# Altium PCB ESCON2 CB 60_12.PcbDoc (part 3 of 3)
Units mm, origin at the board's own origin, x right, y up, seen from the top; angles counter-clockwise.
Board outline 65.5 x 41 mm, 8 copper layers (Top Side, Mid Layer 1, Mid Layer 2, Mid Layer 3, Mid Layer 4, Mid Layer 5, Mid Layer 6, Bottom Side), stack 1.555 mm thick; 142 components, 77 nets, 455 pads, 2194 vias.
Unrouted connection lines stored in the file: 71.
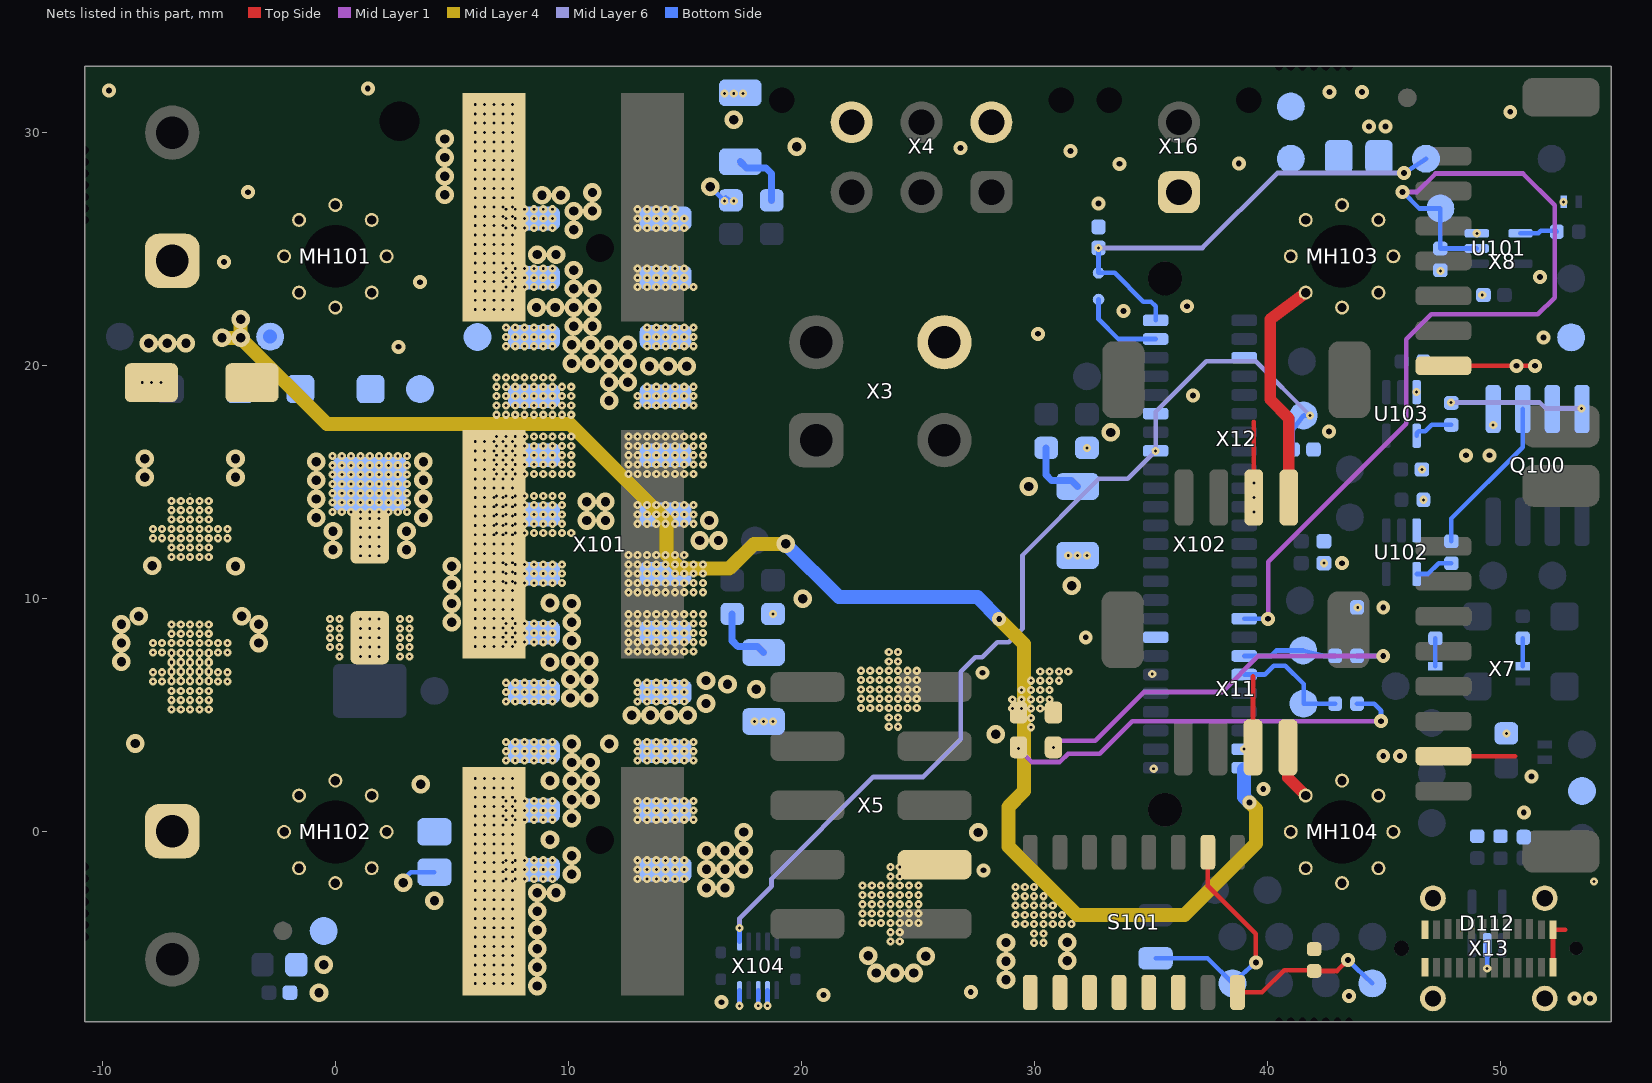
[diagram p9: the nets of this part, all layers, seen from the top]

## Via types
v1: diameter 0.35, hole 0.125, Mid Layer 6 to Bottom Side, tented both sides, 1058 vias
v2: diameter 0.35, hole 0.125, Top Side to Mid Layer 1, tented both sides, 820 vias
v3: diameter 0.8, hole 0.4, Top Side to Bottom Side, 205 vias
v4: diameter 0.6, hole 0.25, Top Side to Bottom Side, 111 vias

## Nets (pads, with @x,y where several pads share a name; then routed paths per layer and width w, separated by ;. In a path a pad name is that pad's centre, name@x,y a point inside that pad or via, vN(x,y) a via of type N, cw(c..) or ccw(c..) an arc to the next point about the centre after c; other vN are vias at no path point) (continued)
GND: C101.2 C102.2 C103.2 C104.2 C106.1 C108.1 C112.1 C113.1 C114.1 C115.1 C116.1 C119.1 C122.1 C123.1 C124.1 C125.1 C126.2 D101.2 D104.2 D106.1 D112.2 D113.1 D114.1 DS101.1 DS102.1 Q100.1 Q100.3 R102.1 R103.1 R105.1 R107.2 R108.2 R117.1 R118.1 R119.1 R120.1 R121.1 S101.1 S101.2 S101.3 S101.4 S101.5 S101.6 TP101.1 TP116.1 TP125.1 TP149.1 U101.3 U102.3 U103.3 X1.1 X2.1 X4.4 X5.3 X7.7 X8.7 X11.3 X12.3 X13.A1 X13.A12 X13.B1 X13.B12 X16.1 X101.1 X101.7 X101.13 X101.23 X101.24 X102.3 X102.16 X102.40 X102.45 X104.3 X104.5 X104.9 | length 20.4
  Top Side w0.2: X11.3@39.379,3.625 39.379,6.685 ; v2(39.415,14.972) 39.415,17.599 ; X7.7@47.55,3.25 50.624,3.25 ; X8.7@47.55,20 v4(50.687,20) v4(51.477,20) ; X13.B1@52.25,-5.805 X13.A12@52.25,-4.195 52.779,-4.195
  Bottom Side w0.2: v3@2.872,-2.088 3.231,-1.73 C108.1@4.25,-1.73 ; v3(16.083,27.687) 16.693,27.076 v1(16.697,27.076) ; C113.1@16.747,27.221 ccw(c17.097,27.572) v1(17.097,27.076) ; v1@17.345,-7.384 X104.9@17.345,-6.795 ; v1@18.145,-7.38 X104.5@18.145,-6.795 ; v1@18.545,-7.38 X104.3@18.545,-6.795 ; v1(49.429,-5.86) D112.2@49.429,-4.867 ; v4@51.292,2.382 v4(51.325,2.382)
  other v1: 17.345,-7.464 18.145,-7.46 18.545,-7.46 29.985,-4.76 30.385,-4.76 29.985,-4.36 30.385,-4.36 29.185,-3.96 29.585,-3.96 29.985,-3.96 30.385,-3.96 30.785,-3.96 31.185,-3.96 31.585,-3.96 29.185,-3.56 29.585,-3.56 29.985,-3.56 30.385,-3.56 30.785,-3.56 31.185,-3.56 29.185,-3.16 29.585,-3.16 29.985,-3.16 30.385,-3.16 30.785,-3.16 29.185,-2.76 29.585,-2.76 29.985,-2.76 30.385,-2.76 29.185,-2.36 29.585,-2.36 29.985,-2.36 12.972,-2.02 13.372,-2.02 13.772,-2.02 14.172,-2.02 14.572,-2.02 14.972,-2.02 12.972,-1.62 13.372,-1.62 13.772,-1.62 14.172,-1.62 14.572,-1.62 14.972,-1.62 12.972,-1.22 13.372,-1.22 13.772,-1.22 14.172,-1.22 14.572,-1.22 14.972,-1.22 39,3.55 50.25,4.225 29.85,4.488 17.98,4.738 18.38,4.738 18.78,4.738 29.85,4.888 -7.033,5.25 -6.633,5.25 -6.233,5.25 -5.833,5.25 -5.433,5.25 29.05,5.288 29.45,5.288 29.85,5.288 30.25,5.288 12.972,5.6 13.372,5.6 13.772,5.6 14.172,5.6 14.572,5.6 14.972,5.6 -7.033,5.65 -6.633,5.65 -6.233,5.65 -5.833,5.65 -5.433,5.65 29.05,5.688 29.45,5.688 29.85,5.688 30.25,5.688 30.65,5.688 12.972,6 13.372,6 13.772,6 14.172,6 14.572,6 14.972,6 -7.033,6.05 -6.633,6.05 -6.233,6.05 -5.833,6.05 -5.433,6.05 29.45,6.088 29.85,6.088 30.25,6.088 30.65,6.088 12.972,6.4 13.372,6.4 13.772,6.4 14.172,6.4 14.572,6.4 14.972,6.4 -7.833,6.45 -7.433,6.45 -7.033,6.45 -6.633,6.45 -6.233,6.45 -5.833,6.45 -5.433,6.45 -5.033,6.45 -4.633,6.45 29.85,6.488 30.25,6.488 30.65,6.488 31.05,6.488 -7.833,6.85 -7.433,6.85 -7.033,6.85 -6.633,6.85 -6.233,6.85 -5.833,6.85 -5.433,6.85 -5.033,6.85 -4.633,6.85 30.25,6.888 30.65,6.888 31.05,6.888 31.45,6.888 -7.033,7.25 -6.633,7.25 -6.233,7.25 -5.833,7.25 -5.433,7.25 -7.033,7.65 -6.633,7.65 -6.233,7.65 -5.833,7.65 -5.433,7.65 18.78,9.352 43.872,9.631 42.42,11.53 31.451,11.862 31.851,11.862 32.251,11.862 12.972,13.22 13.372,13.22 13.772,13.22 14.172,13.22 14.572,13.22 14.972,13.22 15.372,13.22 12.972,13.62 13.372,13.62 13.772,13.62 14.172,13.62 14.572,13.62 14.972,13.62 15.372,13.62 12.972,14.02 13.372,14.02 13.772,14.02 14.172,14.02 14.572,14.02 14.972,14.02 15.372,14.02 46.69,14.25 46.625,15.55 32.251,16.476 49.685,17.465 46.4,18.87 49.217,23.036 47.417,24.066 48.982,25.686 7.32,25.92 7.72,25.92 8.12,25.92 8.52,25.92 8.92,25.92 9.32,25.92 12.972,25.92 13.372,25.92 13.772,25.92 14.172,25.92 14.572,25.92 14.972,25.92 7.32,26.32 7.72,26.32 8.12,26.32 8.52,26.32 8.92,26.32 9.32,26.32 12.972,26.32 13.372,26.32 13.772,26.32 14.172,26.32 14.572,26.32 14.972,26.32 7.32,26.72 7.72,26.72 8.12,26.72 8.52,26.72 8.92,26.72 9.32,26.72 12.972,26.72 13.372,26.72 13.772,26.72 14.172,26.72 14.572,26.72 52.707,27.036 16.697,31.691 17.097,31.691 17.497,31.691
  other v2: 54.009,-2.135 35.116,2.708 -7.033,6.5 -6.633,6.5 -6.233,6.5 -5.833,6.5 -5.433,6.5 35.056,6.772 -7.033,6.9 -6.633,6.9 -6.233,6.9 -5.833,6.9 -5.433,6.9 -7.033,7.3 -6.633,7.3 -6.233,7.3 -5.833,7.3 -5.433,7.3 0.176,7.53 1.076,7.53 1.476,7.53 1.876,7.53 2.776,7.53 3.176,7.53 -7.833,7.7 -7.433,7.7 -7.033,7.7 -6.633,7.7 -6.233,7.7 -5.833,7.7 -5.433,7.7 -5.033,7.7 -4.633,7.7 -0.224,7.93 0.176,7.93 1.076,7.93 1.476,7.93 1.876,7.93 2.776,7.93 3.176,7.93 -7.833,8.1 -7.433,8.1 -7.033,8.1 -6.633,8.1 -6.233,8.1 -5.833,8.1 -5.433,8.1 -5.033,8.1 -4.633,8.1 -0.224,8.33 0.176,8.33 1.076,8.33 1.476,8.33 1.876,8.33 2.776,8.33 3.176,8.33 -7.033,8.5 -6.633,8.5 -6.233,8.5 -5.833,8.5 -5.433,8.5 -0.224,8.73 0.176,8.73 1.076,8.73 1.476,8.73 1.876,8.73 2.776,8.73 3.176,8.73 -7.033,8.9 -6.633,8.9 -6.233,8.9 -5.833,8.9 -5.433,8.9 -0.224,9.13 0.176,9.13 1.076,9.13 1.476,9.13 1.876,9.13 2.776,9.13 3.176,9.13 39.415,13.727 39.415,14.35 -8.288,19.278 -7.888,19.278 -7.488,19.278
  other v3: -0.7,-6.9 28.776,-6.351 -0.5,-5.7 28.776,-5.551 31.403,-5.534 28.776,-4.751 31.403,-4.734 4.25,-2.95 15.924,-2.409 16.724,-2.409 2.91,-2.18 15.924,-1.609 16.724,-1.609 17.524,-1.609 15.924,-0.809 16.724,-0.809 17.524,-0.809 27.592,-0.024 17.524,-0.009 3.663,2.043 -8.582,3.795 28.34,4.193 12.72,5.007 13.52,5.007 14.32,5.007 15.12,5.007 15.906,5.508 18.065,6.114 16.826,6.336 15.906,6.492 -9.182,7.304 -9.182,8.104 -3.285,8.104 -9.182,8.904 -3.285,8.904 -8.444,9.249 -4.023,9.249 20.05,10.01 31.605,10.568 15.637,12.506 16.437,12.506 10.788,13.36 11.588,13.36 16.047,13.36 10.788,14.16 11.588,14.16 29.75,14.822 33.274,17.141 -8.014,20.963 -7.214,20.963 -6.414,20.963 10.23,25.84 10.23,26.64 11.03,26.64 8.868,27.313 9.668,27.313 4.697,27.337 11.03,27.44 4.697,28.137 4.697,28.937 19.798,29.396 4.697,29.737 17.097,30.561
  other v4: 16.564,-7.311 53.167,-7.141 53.838,-7.149 43.5,-7.05 20.948,-7.005 27.267,-6.867 27.818,-1.65 51,0.826 39.818,1.832 44.968,3.25 45.692,3.25 27.776,6.828 32.201,8.35 44.968,9.631 43.2,11.53 48.525,16.159 49.527,16.159 42.636,17.187 36.799,18.723 2.708,20.814 51.84,21.22 30.154,21.373 33.815,22.348 36.552,22.556 3.636,23.586 51.697,23.815 -4.781,24.46 32.751,26.967 -3.744,27.45 33.655,28.668 38.77,28.686 31.546,29.216 26.822,29.352 44.362,30.276 45.062,30.276 50.417,30.9 42.66,31.75 44.05,31.75 -9.716,31.82 1.392,31.901
LED_Axis_gn: R110.1 TP142.1 X102.13 | length 4
  Bottom Side w0.2: X102.13@39,7.55 40.15,7.55 40.38,7.78 TP142.1@41.529,7.78 42.42,7.55 R110.1@42.902,7.55
LED_Axis_rd: R109.1 TP141.1 X102.11 | length 5.2
  Bottom Side w0.2: X102.11@39,6.75 39.889,6.75 40.269,7.13 40.766,7.13 41.55,6.346 TP141.1@41.55,5.5 R109.1@42.902,5.5
NetC107_1: C107.1 R102.2 | length 2.7
  Bottom Side w0.3: R102.2@17.374,28.758 17.639,28.494 18.486,28.494 18.724,28.256 C107.1@18.724,27.104
NetC109_1: C109.1 R103.2 | length 2.7
  Bottom Side w0.3: C109.1@17.03,9.352 17.03,8.2 17.268,7.962 18.115,7.962 R103.2@18.38,7.698
NetC111_1: C111.1 R105.2 | length 2.7
  Bottom Side w0.3: C111.1@30.501,16.476 30.501,15.324 30.739,15.086 31.587,15.086 R105.2@31.851,14.822
NetD108_1: D108.1 R115.2 | length 1.2
  Bottom Side w0.2: D108.1@47.205,7.105 R115.2@47.205,8.31
NetD109_1: D109.1 R116.2 | length 1.2
  Bottom Side w0.2: D109.1@50.955,7.105 R116.2@50.955,8.31
NetDS101_2: DS101.2 R109.2 | length 18.1
  Mid Layer 1 w0.2: v2(29.315,3.574) 29.892,2.997 31.082,2.997 31.442,3.357 32.801,3.357 34.194,4.75 v4(44.872,4.75)
  Bottom Side w0.2: R109.2@43.842,5.5 44.572,5.5 44.872,5.2 v4(44.872,4.75)
NetDS102_2: DS102.2 R110.2 | length 16.9
  Mid Layer 1 w0.2: v2(30.815,3.629) 31.1,3.914 32.602,3.914 34.688,6 38.057,6 39.607,7.55 v4(44.968,7.55)
  Bottom Side w0.2: R110.2@43.842,7.55 v4(44.968,7.55)
NetQ100_2: Q100.2 R112.2 | length 6.9
  Bottom Side w0.2: R112.2@47.89,12.47 47.89,13.447 50.955,16.512 Q100.2@50.955,18.148
NetQ100_4: Q100.4 R114.2 | length 5.7
  Mid Layer 6 w0.2: v1(47.876,18.424) 51.689,18.424 51.946,18.168 v1(53.481,18.168)
NetR104_1: R104.1 S101.10 TP132.1 | length 10.7
  Top Side w0.2: S101.10@37.442,-0.875 37.442,-2.32 39.5,-4.378 v4(39.5,-5.6)
  Bottom Side w0.2: R104.1@35.2,-5.425 37.425,-5.425 TP132.1@38.5,-6.5 v4(39.5,-5.6)
NetR111_2: R111.2 U101.4 | length 1.6
  Bottom Side w0.2: U101.4@50.852,25.686 51.627,25.686 51.731,25.789 52.384,25.789 R111.2@52.417,25.756
NetR112_1: R112.1 U102.4 | length 1.7
  Bottom Side w0.2: U102.4@46.4,11.065 46.878,11.065 47.343,11.53 R112.1@47.89,11.53
NetR114_1: R114.1 U103.4 | length 1.7
  Bottom Side w0.2: U103.4@46.4,17 46.4,17.102 46.485,17.187 46.768,17.187 47.045,17.465 R114.1@47.89,17.465
NetR117_2: R117.2 S101.8 TP134.1 | length 6.8
  Top Side w0.2: S101.8@38.712,-6.889 39.764,-6.889 40.714,-5.939 41.969,-5.939 R117.2@42,-5.97 42.98,-5.97 v4(43.45,-5.5)
  Bottom Side w0.2: v4(43.45,-5.5) TP134.1@44.5,-6.5
S2_Clock: R121.2 TP144.1 U101.2 X102.17 | length 39.2
  Mid Layer 1 w0.2: v4(40.029,9.143) 40.029,11.593 45.952,17.516 45.952,21.131 47.028,22.207 51.603,22.207 52.321,22.925 52.321,26.894 50.966,28.25 47.209,28.25 46.421,27.462 v4(45.798,27.462)
  Bottom Side w0.2: X102.17@39,9.15 39.007,9.143 v4(40.029,9.143) ; v4(45.798,27.462) 46.51,26.75 TP144.1@47.417,26.75 R121.2@47.417,25.036 U101.2@48.982,25.036
SGND: C106.2 C108.2 MH101.2 MH101.3 MH101.4 MH101.5 MH101.6 MH101.7 MH101.8 MH101.9 MH102.2 MH102.3 MH102.4 MH102.5 MH102.6 MH102.7 MH102.8 MH102.9 MH103.2 MH103.3 MH103.4 MH103.5 MH103.6 MH103.7 MH103.8 MH103.9 MH104.2 MH104.3 MH104.4 MH104.5 MH104.6 MH104.7 MH104.8 MH104.9 TP153.1 X3.4 X4.6 X11.4 X12.4 X13.S1 X13.S2 X13.S3 X13.S4 | length 12.3
  Top Side w0.5: X11.4@40.879,3.625 40.879,2.321 MH104.3@41.64,1.56 ; X12.4@40.915,14.35 40.915,17.753 40.115,18.553 40.115,21.992 MH103.5@41.64,23.14
SYS_/Reset: C123.2 TP154.1 X102.36 X104.10 | length 43
  Mid Layer 6 w0.2: v1(17.345,-4.12) 17.345,-3.701 18.718,-2.328 18.718,-2.007 23.082,2.357 25.219,2.357 26.84,3.979 26.84,6.872 27.46,7.492 27.758,7.492 28.401,8.136 28.9,8.136 29.486,8.721 29.486,11.87 32.766,15.15 34,15.15 v1(35.2,16.35) 35.2,18.021 37.379,20.2 39.493,20.2 v1(41.825,17.868)
  Bottom Side w0.2: X104.10@17.345,-4.705 v1(17.345,-4.12) ; C123.2@41.075,16.409 41.075,17.251 TP154.1@41.55,17.868 v1(41.825,17.868)
U: L101.2 TP140.1 X101.17 X101.19 X101.20 X101.21 X101.22
  other v1: 12.972,18.3 13.372,18.3 13.772,18.3 14.172,18.3 14.572,18.3 14.972,18.3 15.372,18.3 12.972,18.7 13.372,18.7 13.772,18.7 14.172,18.7 14.572,18.7 14.972,18.7 15.372,18.7 13.372,19.1 13.772,19.1 14.172,19.1 14.572,19.1 14.972,19.1 15.372,19.1 7.32,20.84 7.72,20.84 8.12,20.84 8.52,20.84 8.92,20.84 9.32,20.84 13.372,20.84 13.772,20.84 14.172,20.84 14.572,20.84 14.972,20.84 15.372,20.84 7.32,21.24 7.72,21.24 8.12,21.24 8.52,21.24 8.92,21.24 9.32,21.24 13.372,21.24 13.772,21.24 14.172,21.24 14.572,21.24 14.972,21.24 15.372,21.24 7.32,21.64 7.72,21.64 8.12,21.64 8.52,21.64 8.92,21.64 9.32,21.64 13.372,21.64 13.772,21.64 14.172,21.64 14.572,21.64 14.972,21.64 15.372,21.64 7.32,23.38 7.72,23.38 8.12,23.38 8.52,23.38 8.92,23.38 9.32,23.38 12.972,23.38 13.372,23.38 13.772,23.38 14.172,23.38 14.572,23.38 14.972,23.38 15.372,23.38 7.32,23.78 7.72,23.78 8.12,23.78 8.52,23.78 8.92,23.78 9.32,23.78 12.972,23.78 13.372,23.78 13.772,23.78 14.172,23.78 14.572,23.78 14.972,23.78 7.32,24.18 7.72,24.18 8.12,24.18 8.52,24.18 8.92,24.18 9.32,24.18 12.972,24.18 13.372,24.18 13.772,24.18 14.172,24.18 14.572,24.18 14.972,24.18
  other v2: 6.002,22.413 6.402,22.413 6.802,22.413 7.202,22.413 7.602,22.413 6.002,22.813 6.402,22.813 6.802,22.813 7.202,22.813 7.602,22.813 6.002,23.213 6.402,23.213 6.802,23.213 7.202,23.213 7.602,23.213 6.002,23.613 6.402,23.613 6.802,23.613 7.202,23.613 7.602,23.613 6.002,24.013 6.402,24.013 6.802,24.013 7.202,24.013 7.602,24.013 6.002,24.413 6.402,24.413 6.802,24.413 7.202,24.413 7.602,24.413 6.002,24.813 6.402,24.813 6.802,24.813 7.202,24.813 7.602,24.813 6.002,25.213 6.402,25.213 6.802,25.213 7.202,25.213 7.602,25.213 6.002,25.613 6.402,25.613 6.802,25.613 7.202,25.613 7.602,25.613 6.002,26.013 6.402,26.013 6.802,26.013 7.202,26.013 7.602,26.013 6.002,26.413 6.402,26.413 6.802,26.413 7.202,26.413 7.602,26.413 6.002,26.813 6.402,26.813 6.802,26.813 7.202,26.813 7.602,26.813 6.002,27.213 6.402,27.213 6.802,27.213 7.202,27.213 7.602,27.213 6.002,27.613 6.402,27.613 6.802,27.613 7.202,27.613 7.602,27.613 6.002,28.013 6.402,28.013 6.802,28.013 7.202,28.013 7.602,28.013 6.002,28.413 6.402,28.413 6.802,28.413 7.202,28.413 7.602,28.413 6.002,28.813 6.402,28.813 6.802,28.813 7.202,28.813 7.602,28.813 6.002,29.213 6.402,29.213 6.802,29.213 7.202,29.213 7.602,29.213 6.002,29.613 6.402,29.613 6.802,29.613 7.202,29.613 7.602,29.613 6.002,30.013 6.402,30.013 6.802,30.013 7.202,30.013 7.602,30.013 6.002,30.413 6.402,30.413 6.802,30.413 7.202,30.413 7.602,30.413 6.002,30.813 6.402,30.813 6.802,30.813 7.202,30.813 7.602,30.813 6.002,31.213 6.402,31.213 6.802,31.213 7.202,31.213 7.602,31.213
  other v3: 11.746,18.5 11.746,19.3 12.546,19.3 13.482,19.98 14.282,19.98 15.082,19.98 10.146,20.1 10.946,20.1 11.746,20.1 12.546,20.1 10.146,20.9 10.946,20.9 11.746,20.9 12.546,20.9 10.23,21.7 11.03,21.7 8.63,22.5 9.43,22.5 10.23,22.5 11.03,22.5 10.23,23.3 11.03,23.3 10.23,24.1 8.668,24.773 9.468,24.773
UART_RxD: C124.2 TP155.1 TPM102.1 X102.50 | length 20.3
  Mid Layer 6 w0.2: v1(32.751,25.059) 37.209,25.059 40.421,28.271 v4(45.865,28.271)
  Bottom Side w0.2: v1(32.751,25.059) TPM102.1@32.751,23.988 33.444,23.988 34.677,22.756 35,22.756 35.2,22.556 X102.50@35.2,21.95 ; v4(45.865,28.271) TP155.1@46.8,28.885
UART_TxD: TPM101.1 X102.48 | length 3.6
  Bottom Side w0.2: TPM101.1@32.751,22.844 32.751,22 33.601,21.15 X102.48@35.2,21.15
V: L102.2 TP139.1 X101.8 X101.9 X101.10 X101.11 X101.12
  other v1: 7.32,5.6 7.72,5.6 8.12,5.6 8.52,5.6 8.92,5.6 9.32,5.6 7.32,6 7.72,6 8.12,6 8.52,6 8.92,6 9.32,6 7.32,6.4 7.72,6.4 8.12,6.4 8.52,6.4 8.92,6.4 9.32,6.4 12.572,7.74 12.972,7.74 13.372,7.74 13.772,7.74 14.172,7.74 14.572,7.74 14.972,7.74 15.372,7.74 7.32,8.14 7.72,8.14 8.12,8.14 8.52,8.14 8.92,8.14 9.32,8.14 12.572,8.14 12.972,8.14 13.372,8.14 13.772,8.14 14.172,8.14 14.572,8.14 14.972,8.14 15.372,8.14 15.772,8.14 7.32,8.54 7.72,8.54 8.12,8.54 8.52,8.54 8.92,8.54 9.32,8.54 12.572,8.54 12.972,8.54 13.372,8.54 13.772,8.54 14.172,8.54 14.572,8.54 14.972,8.54 15.372,8.54 15.772,8.54 7.32,8.94 7.72,8.94 8.12,8.94 8.52,8.94 8.92,8.94 9.32,8.94 12.572,8.94 12.972,8.94 13.372,8.94 13.772,8.94 14.172,8.94 14.572,8.94 14.972,8.94 15.372,8.94 15.772,8.94 12.572,9.34 12.972,9.34 13.372,9.34 13.772,9.34 14.172,9.34 14.572,9.34 14.972,9.34 15.372,9.34 15.772,9.34 12.572,10.28 12.972,10.28 13.372,10.28 13.772,10.28 14.172,10.28 14.572,10.28 14.972,10.28 15.372,10.28 15.772,10.28 7.32,10.68 7.72,10.68 8.12,10.68 8.52,10.68 8.92,10.68 9.32,10.68 9.72,10.68 12.572,10.68 12.972,10.68 13.372,10.68 13.772,10.68 14.172,10.68 14.572,10.68 14.972,10.68 15.372,10.68 15.772,10.68 7.32,11.08 7.72,11.08 8.12,11.08 8.52,11.08 8.92,11.08 9.32,11.08 9.72,11.08 12.572,11.08 12.972,11.08 13.372,11.08 13.772,11.08 14.172,11.08 14.572,11.08 14.972,11.08 15.372,11.08 15.772,11.08 7.32,11.48 7.72,11.48 8.12,11.48 8.52,11.48 8.92,11.48 9.32,11.48 9.72,11.48 12.572,11.48 12.972,11.48 13.372,11.48 13.772,11.48 14.172,11.48 14.572,11.48 14.972,11.48 15.372,11.48 15.772,11.48 12.572,11.88 12.972,11.88 13.372,11.88 13.772,11.88 14.172,11.88 14.572,11.88 14.972,11.88
  other v2: 6.002,7.95 6.402,7.95 6.802,7.95 7.202,7.95 7.602,7.95 6.002,8.35 6.402,8.35 6.802,8.35 7.202,8.35 7.602,8.35 6.002,8.75 6.402,8.75 6.802,8.75 7.202,8.75 7.602,8.75 6.002,9.15 6.402,9.15 6.802,9.15 7.202,9.15 7.602,9.15 6.002,9.55 6.402,9.55 6.802,9.55 7.202,9.55 7.602,9.55 6.002,9.95 6.402,9.95 6.802,9.95 7.202,9.95 7.602,9.95 6.002,10.35 6.402,10.35 6.802,10.35 7.202,10.35 7.602,10.35 6.002,10.75 6.402,10.75 6.802,10.75 7.202,10.75 7.602,10.75 6.002,11.15 6.402,11.15 6.802,11.15 7.202,11.15 7.602,11.15 6.002,11.55 6.402,11.55 6.802,11.55 7.202,11.55 7.602,11.55 6.002,11.95 6.402,11.95 6.802,11.95 7.202,11.95 7.602,11.95 6.002,12.35 6.402,12.35 6.802,12.35 7.202,12.35 7.602,12.35 6.002,12.75 6.402,12.75 6.802,12.75 7.202,12.75 7.602,12.75 6.002,13.15 6.402,13.15 6.802,13.15 7.202,13.15 7.602,13.15 6.002,13.55 6.402,13.55 6.802,13.55 7.202,13.55 7.602,13.55 6.002,13.95 6.402,13.95 6.802,13.95 7.202,13.95 7.602,13.95 6.002,14.35 6.402,14.35 6.802,14.35 7.202,14.35 7.602,14.35 6.002,14.75 6.402,14.75 6.802,14.75 7.202,14.75 7.602,14.75 6.002,15.15 6.402,15.15 6.802,15.15 7.202,15.15 7.602,15.15 6.002,15.55 6.402,15.55 6.802,15.55 7.202,15.55 7.602,15.55 6.002,15.95 6.402,15.95 6.802,15.95 7.202,15.95 7.602,15.95 6.002,16.35 6.402,16.35 6.802,16.35 7.202,16.35 7.602,16.35 6.002,16.75 6.402,16.75 6.802,16.75 7.202,16.75 7.602,16.75
  other v3: 10.088,5.741 10.888,5.741 10.088,6.541 10.888,6.541 9.21,7.28 10.088,7.341 10.888,7.341 10.146,8.2 5,9 10.146,9 5,9.8 10.146,9.8 9.21,9.82 5,10.6 5,11.4
VL: D102.1 D103.1 D104.1 TP106.1 X102.1 | length 67.9
  Mid Layer 4 w0.6: v3(-4.865,21.201) v3(-4.065,21.201) ; v3(-4.065,22.001) v3(-4.065,21.201) ; v3(19.323,12.362) 17.968,12.362 16.902,11.296 14.81,11.296 14.203,11.903 14.203,13.36 10.062,17.5 -0.364,17.5 v3(-4.065,21.201) ; v4(28.486,9.136) 29.561,8.061 29.561,1.762 28.876,1.078 28.876,-0.626 31.826,-3.575 36.431,-3.575 39.512,-0.494 39.512,0.974 v4(39.23,1.256)
  Bottom Side w0.6: v3(19.323,12.362) 21.61,10.075 27.546,10.075 v4(28.486,9.136) ; X102.1@39,2.677 39,1.486 v4(39.23,1.256)
VP: C101.1 C102.1 C103.1 C104.1 D101.1 D103.2 F101.2 TP104.1 X101.14 X101.15 X101.16 X101.18
  other v1: 23.82,-4.708 24.22,-4.708 23.82,-4.308 24.22,-4.308 22.62,-3.908 23.02,-3.908 23.42,-3.908 23.82,-3.908 24.22,-3.908 24.62,-3.908 25.02,-3.908 22.62,-3.508 23.02,-3.508 23.42,-3.508 23.82,-3.508 24.22,-3.508 24.62,-3.508 25.02,-3.508 22.62,-3.108 23.02,-3.108 23.42,-3.108 23.82,-3.108 24.22,-3.108 24.62,-3.108 25.02,-3.108 22.62,-2.708 23.02,-2.708 23.42,-2.708 23.82,-2.708 24.22,-2.708 24.62,-2.708 25.02,-2.708 22.62,-2.308 23.02,-2.308 23.42,-2.308 23.82,-2.308 24.22,-2.308 24.62,-2.308 25.02,-2.308 23.82,-1.908 24.22,-1.908 23.82,-1.508 24.22,-1.508 23.75,4.514 24.15,4.514 23.75,4.914 24.15,4.914 22.55,5.314 22.95,5.314 23.35,5.314 23.75,5.314 24.15,5.314 24.55,5.314 24.95,5.314 22.55,5.714 22.95,5.714 23.35,5.714 23.75,5.714 24.15,5.714 24.55,5.714 24.95,5.714 22.55,6.114 22.95,6.114 23.35,6.114 23.75,6.114 24.15,6.114 24.55,6.114 24.95,6.114 22.55,6.514 22.95,6.514 23.35,6.514 23.75,6.514 24.15,6.514 24.55,6.514 24.95,6.514 22.55,6.914 22.95,6.914 23.35,6.914 23.75,6.914 24.15,6.914 24.55,6.914 24.95,6.914 23.75,7.314 24.15,7.314 23.75,7.714 24.15,7.714 -7.033,11.8 -6.633,11.8 -6.233,11.8 -5.833,11.8 -5.433,11.8 -7.033,12.2 -6.633,12.2 -6.233,12.2 -5.833,12.2 -5.433,12.2 -7.833,12.6 -7.433,12.6 -7.033,12.6 -6.633,12.6 -6.233,12.6 -5.833,12.6 -5.433,12.6 -5.033,12.6 -4.633,12.6 6.92,12.82 7.32,12.82 7.72,12.82 8.12,12.82 8.52,12.82 8.92,12.82 9.32,12.82 9.72,12.82 10.12,12.82 -7.833,13 -7.433,13 -7.033,13 -6.633,13 -6.233,13 -5.833,13 -5.433,13 -5.033,13 -4.633,13 6.92,13.22 7.32,13.22 7.72,13.22 8.12,13.22 8.52,13.22 8.92,13.22 9.32,13.22 9.72,13.22 -7.033,13.4 -6.633,13.4 -6.233,13.4 -5.833,13.4 -5.433,13.4 6.92,13.62 7.32,13.62 7.72,13.62 8.12,13.62 8.52,13.62 8.92,13.62 9.32,13.62 9.72,13.62 -0.124,13.73 0.276,13.73 0.676,13.73 1.076,13.73 1.476,13.73 1.876,13.73 2.276,13.73 2.676,13.73 3.076,13.73 -7.033,13.8 -6.633,13.8 -6.233,13.8 -5.833,13.8 -5.433,13.8 6.92,14.02 7.32,14.02 7.72,14.02 8.12,14.02 8.52,14.02 8.92,14.02 9.32,14.02 9.72,14.02 -0.124,14.13 0.276,14.13 0.676,14.13 1.076,14.13 1.476,14.13 1.876,14.13 2.276,14.13 2.676,14.13 3.076,14.13 -7.033,14.2 -6.633,14.2 -6.233,14.2 -5.833,14.2 -5.433,14.2 6.92,14.42 7.32,14.42 7.72,14.42 8.12,14.42 8.52,14.42 8.92,14.42 9.32,14.42 9.72,14.42 -0.124,14.53 0.276,14.53 0.676,14.53 1.076,14.53 1.476,14.53 1.876,14.53 2.276,14.53 2.676,14.53 3.076,14.53 -0.124,14.93 0.276,14.93 0.676,14.93 1.076,14.93 1.476,14.93 1.876,14.93 2.276,14.93 2.676,14.93 3.076,14.93 -0.124,15.33 0.276,15.33 0.676,15.33 1.076,15.33 1.476,15.33 1.876,15.33 2.276,15.33 2.676,15.33 3.076,15.33 6.92,15.36 7.32,15.36 7.72,15.36 8.12,15.36 8.52,15.36 8.92,15.36 9.32,15.36 9.72,15.36 10.12,15.36 12.572,15.36 12.972,15.36 13.372,15.36 13.772,15.36 14.172,15.36 14.572,15.36 14.972,15.36 15.372,15.36 -0.124,15.73 0.276,15.73 0.676,15.73 1.076,15.73 1.476,15.73 1.876,15.73 2.276,15.73 2.676,15.73 3.076,15.73 6.92,15.76 7.32,15.76 7.72,15.76 8.12,15.76 8.52,15.76 8.92,15.76 9.32,15.76 9.72,15.76 10.12,15.76 12.572,15.76 12.972,15.76 13.372,15.76 13.772,15.76 14.172,15.76 14.572,15.76 14.972,15.76 15.372,15.76 15.772,15.76 -0.124,16.13 0.276,16.13 0.676,16.13 1.076,16.13 1.476,16.13 1.876,16.13 2.276,16.13 2.676,16.13 3.076,16.13 6.92,16.16 7.32,16.16 7.72,16.16 8.12,16.16 8.52,16.16 8.92,16.16 9.32,16.16 9.72,16.16 10.12,16.16 12.572,16.16 12.972,16.16 13.372,16.16 13.772,16.16 14.172,16.16 14.572,16.16 14.972,16.16 15.372,16.16 15.772,16.16 6.92,16.56 7.32,16.56 7.72,16.56 8.12,16.56 8.52,16.56 8.92,16.56 9.32,16.56 9.72,16.56 10.12,16.56 12.572,16.56 12.972,16.56 13.372,16.56 13.772,16.56 14.172,16.56 14.572,16.56 14.972,16.56 15.372,16.56 15.772,16.56 6.92,16.96 7.32,16.96 7.72,16.96 8.12,16.96 8.52,16.96 8.92,16.96 9.32,16.96 9.72,16.96 10.12,16.96 12.572,16.96 12.972,16.96 13.372,16.96 13.772,16.96 14.172,16.96 14.572,16.96 14.972,16.96 15.372,16.96 15.772,16.96 6.92,17.9 7.32,17.9 7.72,17.9 8.12,17.9 8.52,17.9 8.92,17.9 9.32,17.9 9.72,17.9 10.12,17.9 6.92,18.3 7.32,18.3 7.72,18.3 8.12,18.3 8.52,18.3 8.92,18.3 9.32,18.3 9.72,18.3 10.12,18.3 6.92,18.7 7.32,18.7 7.72,18.7 8.12,18.7 8.52,18.7 8.92,18.7 9.32,18.7 9.72,18.7 10.12,18.7 6.92,19.1 7.32,19.1 7.72,19.1 8.12,19.1 8.52,19.1 8.92,19.1 9.32,19.1 9.72,19.1 10.12,19.1 6.92,19.5 7.32,19.5 7.72,19.5 8.12,19.5 8.52,19.5 8.92,19.5 9.32,19.5
  other v2: 1.076,11.85 1.476,11.85 1.876,11.85 1.076,12.25 1.476,12.25 1.876,12.25 1.076,12.65 1.476,12.65 1.876,12.65 1.076,13.05 1.476,13.05 1.876,13.05 1.076,13.45 1.476,13.45 1.876,13.45
  other v3: 23.215,-6.057 24.015,-6.057 24.815,-6.057 25.334,-5.331 22.871,-5.318 -4.283,11.4 -7.863,11.421 -0.101,12.103 3.053,12.103 -0.101,12.903 3.053,12.903 -0.826,13.484 3.779,13.484 -0.826,14.284 3.779,14.284 -0.826,15.084 3.779,15.084 -8.183,15.211 -4.283,15.211 -0.826,15.884 3.779,15.884 -8.183,16.011 -4.283,16.011
W: L103.2 TP138.1 X101.2 X101.3 X101.4 X101.5 X101.6
  other v1: 7.32,-2.02 7.72,-2.02 8.12,-2.02 8.52,-2.02 8.92,-2.02 9.32,-2.02 7.32,-1.62 7.72,-1.62 8.12,-1.62 8.52,-1.62 8.92,-1.62 9.32,-1.62 7.32,-1.22 7.72,-1.22 8.12,-1.22 8.52,-1.22 8.92,-1.22 9.32,-1.22 7.32,0.52 7.72,0.52 8.12,0.52 8.52,0.52 8.92,0.52 9.32,0.52 12.972,0.52 13.372,0.52 13.772,0.52 14.172,0.52 14.572,0.52 14.972,0.52 15.372,0.52 7.32,0.92 7.72,0.92 8.12,0.92 8.52,0.92 8.92,0.92 9.32,0.92 12.972,0.92 13.372,0.92 13.772,0.92 14.172,0.92 14.572,0.92 14.972,0.92 15.372,0.92 7.32,1.32 7.72,1.32 8.12,1.32 8.52,1.32 8.92,1.32 9.32,1.32 12.972,1.32 13.372,1.32 13.772,1.32 14.172,1.32 14.572,1.32 14.972,1.32 15.372,1.32 7.32,3.06 7.72,3.06 8.12,3.06 8.52,3.06 8.92,3.06 9.32,3.06 12.972,3.06 13.372,3.06 13.772,3.06 14.172,3.06 14.572,3.06 14.972,3.06 15.372,3.06 7.32,3.46 7.72,3.46 8.12,3.46 8.52,3.46 8.92,3.46 9.32,3.46 12.972,3.46 13.372,3.46 13.772,3.46 14.172,3.46 14.572,3.46 14.972,3.46 15.372,3.46 7.32,3.86 7.72,3.86 8.12,3.86 8.52,3.86 8.92,3.86 9.32,3.86 12.972,3.86 13.372,3.86 13.772,3.86 14.172,3.86 14.572,3.86 14.972,3.86 15.372,3.86
  other v2: 6.002,-6.513 6.402,-6.513 6.802,-6.513 7.202,-6.513 7.602,-6.513 6.002,-6.113 6.402,-6.113 6.802,-6.113 7.202,-6.113 7.602,-6.113 6.002,-5.713 6.402,-5.713 6.802,-5.713 7.202,-5.713 7.602,-5.713 6.002,-5.313 6.402,-5.313 6.802,-5.313 7.202,-5.313 7.602,-5.313 6.002,-4.913 6.402,-4.913 6.802,-4.913 7.202,-4.913 7.602,-4.913 6.002,-4.513 6.402,-4.513 6.802,-4.513 7.202,-4.513 7.602,-4.513 6.002,-4.113 6.402,-4.113 6.802,-4.113 7.202,-4.113 7.602,-4.113 6.002,-3.713 6.402,-3.713 6.802,-3.713 7.202,-3.713 7.602,-3.713 6.002,-3.313 6.402,-3.313 6.802,-3.313 7.202,-3.313 7.602,-3.313 6.002,-2.913 6.402,-2.913 6.802,-2.913 7.202,-2.913 7.602,-2.913 6.002,-2.513 6.402,-2.513 6.802,-2.513 7.202,-2.513 7.602,-2.513 6.002,-2.113 6.402,-2.113 6.802,-2.113 7.202,-2.113 7.602,-2.113 6.002,-1.713 6.402,-1.713 6.802,-1.713 7.202,-1.713 7.602,-1.713 6.002,-1.313 6.402,-1.313 6.802,-1.313 7.202,-1.313 7.602,-1.313 6.002,-0.913 6.402,-0.913 6.802,-0.913 7.202,-0.913 7.602,-0.913 6.002,-0.513 6.402,-0.513 6.802,-0.513 7.202,-0.513 7.602,-0.513 6.002,-0.113 6.402,-0.113 6.802,-0.113 7.202,-0.113 7.602,-0.113 6.002,0.287 6.402,0.287 6.802,0.287 7.202,0.287 7.602,0.287 6.002,0.687 6.402,0.687 6.802,0.687 7.202,0.687 7.602,0.687 6.002,1.087 6.402,1.087 6.802,1.087 7.202,1.087 7.602,1.087 6.002,1.487 6.402,1.487 6.802,1.487 7.202,1.487 7.602,1.487 6.002,1.887 6.402,1.887 6.802,1.887 7.202,1.887 7.602,1.887 6.002,2.287 6.402,2.287 6.802,2.287 7.202,2.287 7.602,2.287
  other v3: 8.668,-6.613 8.668,-5.813 8.668,-5.013 8.668,-4.213 8.668,-3.413 8.668,-2.613 9.468,-2.613 10.146,-1.82 10.146,-1.02 9.21,-0.34 10.146,0.58 10.146,1.38 10.946,1.38 10.146,2.18 10.946,2.18 9.21,2.2 10.146,2.98 10.946,2.98 10.146,3.78 11.746,3.78
pads on no net: FD101.1 FD102.1 FD103.1 FD104.1 MH101.1 MH102.1 MH103.1 MH104.1 MH105.1 STEG101.0 STEG102.0 STEG103.0 STEG104.0 U101.1 X4.0 X5.9 X7.0 X8.0 X11.0 X12.0 X13.0 X13.A2 X13.A3 X13.A8 X13.A10 X13.A11 X13.B2 X13.B3 X13.B8 X13.B10 X13.B11 X16.0 X101.0 X102.0 X104.0 X104.6 X104.7 X104.8

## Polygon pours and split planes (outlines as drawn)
GND on Bottom Side "NONET_L-01_P-001" (solid, remove dead copper, pour order 55): -10.75,32.85 -10.75,-8.15 54.75,-8.15 54.75,32.85
C_VP on Bottom Side "NONET_L-01_P-001" (solid, remove dead copper, pour order 9): -8.5,2.5 -10.75,2.5 -10.75,-8.25 -2.6,-8.25 -2.5,-8.15 -2.5,-1.626 1.876,2.75 5,2.75 5,6.826 2.326,9.5 -1.5,9.5
VP on Bottom Side "NONET_L-01_P-001" (solid, remove dead copper, pour order 43): 26.5,-5.194 25.144,-6.55 21.6,-6.55 20.547,-5.498 20.547,7.835 21.653,8.94 24.861,8.94 26.5,7.301
C_W1 on Bottom Side "NONET_L-01_P-001" (solid, remove dead copper, pour order 41): 8.12,32.913 8.12,28.588 8.668,28.04 13.947,28.04 15.169,26.818 15.169,25.65 16.488,24.331 19.031,24.331 19.75,25.05 19.75,26.101 19.5,26.351 17.365,26.351 15.852,27.864 15.852,32.85
C_VDigIO on Bottom Side "NONET_L-01_P-001" (solid, remove dead copper, pour order 40): 54.75,4.187 54.75,3.997 53.628,2.875 51.9,2.875 51.9,2.513 50.655,1.269 50.113,1.269 47.818,3.564 47.818,7.745 54.75,7.745
C_DigOUT1 on Bottom Side "NONET_L-01_P-001" (solid, remove dead copper, pour order 38): 47.161,10.008 46.69,10.008 46.203,9.52 46.203,9.233 47.537,7.899 50.495,7.899 50.495,10.605 51.59,11.7 51.59,15 49.5,15 48.847,14.347 48.847,11.694
C_DigOUT2 on Bottom Side "NONET_L-01_P-001" (solid, remove dead copper, pour order 37): 50.495,8.78 51.376,7.899 54.75,7.899 54.75,14.25 54,15 51.59,15 51.59,11.7 50.495,10.605
SGND on Bottom Side "NONET_L-01_P-001" (solid, remove dead copper, pour order 2): 0,2.75 1.75,2.75 3.25,1.25 4.92,1.25 5.25,0.92 5.25,-0.615 4.865,-1 3.25,-1 1.5,-2.75 0,-2.75
C_W2 on Bottom Side "NONET_L-01_P-001" (solid, remove dead copper, pour order 42): 19.282,10.077 19.282,13.508 18.773,14.016 17.03,15.76 16.215,15.76 15.818,15.362 15.818,10.889 16.63,10.077
U on Bottom Side "NONET_L-01_P-001" (solid, remove dead copper, pour order 12): 14.462,25.05 16,23.512 16,21.413 16,17.5 12.5,17.5 9.9,20.1 4.5,20.1 4.5,24.343 5.207,25.05
W on Bottom Side "NONET_L-01_P-001" (solid, remove dead copper, pour order 10): 15.585,4.25 16,3.835 16,0 15.65,-0.35 12.413,-0.35 9.468,-3.295 9.468,-8.15 5.25,-8.15 5.25,4.25
SGND on Bottom Side "NONET_L-01_P-001" (solid, remove dead copper, pour order 3): 40.45,26.26 40.45,26.742 40,27.192 40,29.015 40.707,29.722 44.04,29.725 44.5,29.265 44.5,27.65 45.95,26.2 45.95,24.7 40.45,24.7
C_W3 on Bottom Side "NONET_L-01_P-001" (solid, remove dead copper, pour order 44): 33.323,17.773 32.751,17.201 29.546,17.201 27.167,14.822 24.848,14.822 23.91,15.76 23.91,17.528 25.382,19 29.25,19 30.6,20.35 32.54,20.35 33.323,19.566
V on Bottom Side "NONET_L-01_P-001" (solid, remove dead copper, pour order 11): 16,7.945 15.145,7.09 13.175,7.09 10.339,4.255 9.91,4.25 5.25,4.25 5.25,6.95 2.425,9.775 4.79,12.14 15.5,12.14 16,11.64
VP on Bottom Side "NONET_L-01_P-001" (solid, remove dead copper, pour order 8): -7,17.5 -9.25,15.25 -9.25,10.5 -8.5,9.75 2.25,9.75 4.85,12.35 10.1,12.35 12.5,14.75 15.5,14.75 16,15.25 16,17.5 12.5,17.5 10,20 1.005,20 -1.495,17.5
VL on Bottom Side "NONET_L-01_P-001" (solid, remove dead copper, pour order 46): -4.083,22.593 -2.725,22.593 0.372,19.497 -1.375,17.75 -4.538,17.75 -5.478,18.69 -5.478,21.198
W on Mid Layer 5 "W" (solid, remove dead copper, pour order 87): -10.75,32.85 -10.75,-8.15 54.75,-8.15 54.75,32.85
C_W3 on Mid Layer 5 "C_W3" (solid, remove dead copper, pour order 86): -10.75,32.85 -10.75,-8.15 54.75,-8.15 54.75,32.85
V on Mid Layer 5 "V" (solid, remove dead copper, pour order 85): -10.75,32.85 -10.75,-8.15 54.75,-8.15 54.75,32.85
U on Mid Layer 5 "U" (solid, remove dead copper, pour order 83): -10.75,32.85 -10.75,-8.15 54.75,-8.15 54.75,32.85
C_W1 on Mid Layer 5 "C_W1" (solid, remove dead copper, pour order 82): -10.75,32.85 -10.75,-8.15 54.75,-8.15 54.75,32.85
GND on Mid Layer 5 "GND" (solid, remove dead copper, pour order 81): -10.75,32.85 -10.75,-8.15 54.75,-8.15 54.75,32.85
SGND on Mid Layer 5 "Mid Layer 5-SGND" (solid, remove dead copper, pour order 4): 5.207,19.702 -0.697,19.702 -3.15,22.155 -3.15,26.726 -2.026,27.85 -0.644,29.232 2.416,29.232 9.895,21.753 9.895,20.922 10.86,19.956 15.056,19.956 15.283,19.729 15.283,23.533 20.5,28.75 20.5,30.552 21.448,31.5 22.804,31.5 23.693,30.611 23.693,28.72 24.564,27.85 45.226,27.85 46.35,26.726 46.35,12.91 47.195,12.015 47.195,5.055 52.741,-0.491 52.741,-8.25 46.676,-8.25 44.126,-5.7 43.2,-4.774 43.2,24.7 29.604,24.7 28.154,23.25 28.154,19.803 27.351,19 25.003,19 24.083,19.92 24.083,22.772 23.038,23.816 20.895,23.816 19,21.921 19,19.535 15.556,16.092 8.817,16.092
SGND on Mid Layer 5 "NONET_L-01_P-001" (solid, remove dead copper, pour order 53): 0.595,-2.145 0,-2.739 -2.436,-2.739 -4.023,-1.153 -4.023,11.477 -3.15,12.35 -3.15,26.726 -2.026,27.85 0,27.85 0,11.441 0.595,10.846
GND on Mid Layer 6 "NONET_L-01_P-001" (solid, remove dead copper, pour order 57): -10.75,32.85 -10.75,-8.15 54.75,-8.15 54.75,32.85
C_VP on Mid Layer 6 "NONET_L-01_P-001" (solid, remove dead copper, pour order 14): -1.5,9.5 2.326,9.5 5,6.826 5,2.75 1.876,2.75 -2.5,-1.626 -2.5,-8.15 -2.6,-8.25 -10.75,-8.25 -10.75,0.25
VP on Mid Layer 6 "NONET_L-01_P-001" (solid, remove dead copper, pour order 13): 12.5,17.5 18.67,17.5 26.087,10.083 26.087,4.694 25.292,3.898 22.52,3.898 19.286,7.132 19.286,10.964 15.5,14.75 12.5,14.75 10.1,12.35 4.85,12.35 2.25,9.75 -8.5,9.75 -9.25,10.5 -9.25,17 -1.995,17 1.005,20 10,20
U on Mid Layer 6 "NONET_L-01_P-001" (solid, remove dead copper, pour order 54): 13.372,25.05 14.45,25.05 16,23.5 16,17.5 12.5,17.5 9.9,20.1 4.5,20.1 4.5,24.343 5.207,25.05
W on Mid Layer 6 "NONET_L-01_P-001" (solid, remove dead copper, pour order 15): 15.585,4.25 16,3.835 16,2.125 16,0 15.65,-0.35 12.413,-0.35 9.468,-3.295 9.468,-8.15 5.25,-8.15 5.25,4.25
V on Mid Layer 6 "NONET_L-01_P-001" (solid, remove dead copper, pour order 16): 13.175,7.09 10.334,4.25 5.25,4.25 5.25,6.95 2.425,9.775 4.79,12.14 15.5,12.14 16,11.64 16,7.945 15.145,7.09
VP on Mid Layer 6 "NONET_L-01_P-001" (solid, remove dead copper, pour order 7): 23.326,-1.014 22.206,-2.134 22.206,-5.903 22.871,-6.55 25.144,-6.55 26.5,-5.194 26.5,-2.76 24.754,-1.014
GND on Top Side "NONET_L-01_P-001" (solid, remove dead copper, pour order 48): -10.75,32.85 -10.75,-8.15 54.75,-8.15 54.75,32.85
V on Top Side "NONET_L-01_P-001" (solid, remove dead copper, pour order 21): 4.552,19.75 8.851,19.75 11.03,17.571 11.03,8.116 12.146,7 12.146,4.5 8.5,4.5 8.5,4.507 8,5.007 4.552,5.007
C_W2 on Top Side "NONET_L-01_P-001" (solid, remove dead copper, pour order 18): 10.646,17.955 11.977,17.955 13.403,19.38 15.424,19.38 16.056,20.012 16.056,23.613 23.137,23.613 24.25,22.5 24.25,14.5 19.936,10.186 16.75,7 12.146,7 10.646,8.5
C_W3 on Top Side "NONET_L-01_P-001" (solid, remove dead copper, pour order 35): 9.32,-8.15 16,-8.15 16,2.727 14.431,4.296 12.146,4.296 9.32,1.47
W on Top Side "NONET_L-01_P-001" (solid, remove dead copper, pour order 22): 4.552,5.007 4.552,-8.213 9.32,-8.213 9.32,-3.418 10.5,-2.238 10.5,0.16 11.426,1.087 11.426,2.74 12.146,3.46 12.146,5.007
C_W1 on Top Side "NONET_L-01_P-001" (solid, remove dead copper, pour order 20): 16.5,32.913 16.5,28.04 15.852,27.392 15.852,20.894 15.784,20.825 13.356,20.825 8.63,25.551 8.63,32.913
VL on Top Side "NONET_L-01_P-001" (solid, remove dead copper, pour order 45): -3.428,22.593 -1.768,20.933 -1.768,18.603 -2.433,17.937 -4.936,17.937 -5.582,18.583 -5.582,21.75 -4.739,22.593
VP on Top Side "NONET_L-01_P-001" (solid, remove dead copper, pour order 36): -4.783,17.25 -3.428,15.895 -3.428,11.552 -4.023,10.957 -8.432,10.957 -9.182,11.707 -9.182,15.943 -7.875,17.25
VP on Top Side "NONET_L-01_P-001" (solid, remove dead copper, pour order 17): 0.605,16.75 -1.029,16.75 -1.5,16.279 -1.5,12.75 0.293,10.957 2.484,10.957 4.25,12.724 4.25,16.279 3.779,16.75
U on Top Side "NONET_L-01_P-001" (solid, remove dead copper, pour order 19): 8.851,19.75 10.501,18.1 14.685,18.1 15.784,19.198 15.784,20.825 13.356,20.825 11.65,22.531 11.65,23.7 9.765,25.586 8.868,25.586 8.63,25.824 8.63,32.913 4.552,32.913 4.552,19.75
W on Mid Layer 3 "W" (solid, remove dead copper, pour order 73): -10.75,32.85 -10.75,-8.15 54.75,-8.15 54.75,32.85
V on Mid Layer 3 "V" (solid, remove dead copper, pour order 71): -10.75,32.85 -10.75,-8.15 54.75,-8.15 54.75,32.85
U on Mid Layer 3 "U" (solid, remove dead copper, pour order 69): -10.75,32.85 -10.75,-8.15 54.75,-8.15 54.75,32.85
GND on Mid Layer 3 "GND" (solid, remove dead copper, pour order 67): -10.75,32.85 -10.75,-8.15 54.75,-8.15 54.75,32.85
C_VP on Mid Layer 3 "NONET_L-01_P-001" (solid, remove dead copper, pour order 23): -3.139,7.861 -0.396,7.861 0.946,6.519 0.946,1.82 -2.5,-1.626 -2.5,-8.15 -2.6,-8.25 -10.75,-8.25 -10.75,0.25
C_W3 on Mid Layer 3 "NONET_L-01_P-001" (solid, remove dead copper, pour order 51): 11.426,3.273 13.16,5.007 16.241,5.007 17.834,6.6 17.834,10.279 23.571,16.016 23.571,18.5 27.655,18.5 29.25,16.905 29.25,3.75 17.35,-8.15 8.668,-8.15 8.668,-3.406 10.19,-1.885 10.19,0.794 11.426,2.03
C_W1 on Mid Layer 3 "NONET_L-01_P-001" (solid, remove dead copper, pour order 26): 11.702,19.98 10.55,21.132 10.662,21.243 10.724,22.997 8.868,24.852 8.868,32.85 18.447,32.913 18.447,29.303 23.375,24.375 23.375,16.125 19.312,12.062 15.283,16.092 15.283,19.467 14.77,19.98
W on Mid Layer 4 "W" (solid, remove dead copper, pour order 80): -10.75,32.85 -10.75,-8.15 54.75,-8.15 54.75,32.85
V on Mid Layer 4 "V" (solid, remove dead copper, pour order 78): -10.75,32.85 -10.75,-8.15 54.75,-8.15 54.75,32.85
U on Mid Layer 4 "U" (solid, remove dead copper, pour order 76): -10.75,32.85 -10.75,-8.15 54.75,-8.15 54.75,32.85
GND on Mid Layer 4 "GND" (solid, remove dead copper, pour order 74): -10.75,32.85 -10.75,-8.15 54.75,-8.15 54.75,32.85
C_W3 on Mid Layer 4 "NONET_L-01_P-001" (solid, remove dead copper, pour order 52): 11.426,3.273 13.16,5.007 16.241,5.007 17.834,6.6 17.834,10.279 23.571,16.016 23.571,18.5 27.655,18.5 29.25,16.905 29.25,3.75 17.35,-8.15 8.668,-8.15 8.668,-3.406 10.19,-1.885 10.19,0.794 11.426,2.03
C_W1 on Mid Layer 4 "NONET_L-01_P-001" (solid, remove dead copper, pour order 27): 15.283,19.187 14.37,20.1 11.83,20.1 10.23,21.7 10.3,24.17 8.868,25.601 8.868,32.85 18.447,32.913 18.447,29.303 23.375,24.375 23.375,16.125 19.312,12.062 15.283,16.092
GND on Mid Layer 1 "NONET_L-01_P-001" (solid, remove dead copper, pour order 56): -10.75,32.85 -10.75,-8.15 54.75,-8.15 54.75,32.85
C_W3 on Mid Layer 1 "NONET_L-01_P-001" (solid, remove dead copper, pour order 49): 9.32,-8.15 16,-8.15 16,2.727 14.431,4.296 12.146,4.296 9.32,1.47
W on Mid Layer 1 "NONET_L-01_P-001" (solid, remove dead copper, pour order 34): 4.552,5.007 4.552,-8.213 9.32,-8.213 9.32,-3.418 10.5,-2.238 10.5,0.16 11.426,1.087 11.426,2.74 12.146,3.46 12.146,5.007
V on Mid Layer 1 "NONET_L-01_P-001" (solid, remove dead copper, pour order 33): 4.552,19.75 8.851,19.75 11.03,17.571 11.03,8.116 12.146,7 12.146,4.5 8.5,4.5 8.5,4.507 8,5.007 4.552,5.007
C_W1 on Mid Layer 1 "NONET_L-01_P-001" (solid, remove dead copper, pour order 32): 16.5,32.913 16.5,28.04 15.852,27.392 15.852,20.894 15.784,20.825 13.356,20.825 8.63,25.551 8.63,32.913
U on Mid Layer 1 "NONET_L-01_P-001" (solid, remove dead copper, pour order 31): 8.851,19.75 10.646,17.955 14.54,17.955 15.784,19.198 15.784,20.825 13.356,20.825 11.65,22.531 11.65,23.7 9.765,25.586 8.868,25.586 8.63,25.824 8.63,32.913 4.552,32.913 4.552,19.75
C_W2 on Mid Layer 1 "NONET_L-01_P-001" (solid, remove dead copper, pour order 30): 10.646,17.735 11.977,17.735 11.977,17.955 13.403,19.38 15.424,19.38 16.056,20.012 16.056,23.613 23.137,23.613 24.25,22.5 24.25,14.5 19.936,10.186 16.75,7 12.146,7 10.646,8.5
VP on Mid Layer 1 "NONET_L-01_P-001" (solid, remove dead copper, pour order 29): 0.605,16.75 -1.029,16.75 -1.5,16.279 -1.5,12.75 0.1,11.15 2.676,11.15 4.25,12.724 4.25,16.279 3.779,16.75
W on Mid Layer 2 "W" (solid, remove dead copper, pour order 66): -10.75,32.85 -10.75,-8.15 54.75,-8.15 54.75,32.85
C_W3 on Mid Layer 2 "C_W3" (solid, remove dead copper, pour order 65): -10.75,32.85 -10.75,-8.15 54.75,-8.15 54.75,32.85
V on Mid Layer 2 "V" (solid, remove dead copper, pour order 64): -10.75,32.85 -10.75,-8.15 54.75,-8.15 54.75,32.85
C_W2 on Mid Layer 2 "C_W2" (solid, remove dead copper, pour order 63): -10.75,32.85 -10.75,-8.15 54.75,-8.15 54.75,32.85
U on Mid Layer 2 "U" (solid, remove dead copper, pour order 62): -10.75,32.85 -10.75,-8.15 54.75,-8.15 54.75,32.85
C_W1 on Mid Layer 2 "C_W1" (solid, remove dead copper, pour order 61): -10.75,32.85 -10.75,-8.15 54.75,-8.15 54.75,32.85
GND on Mid Layer 2 "GND" (solid, remove dead copper, pour order 50): -10.75,32.85 -10.75,-8.15 54.75,-8.15 54.75,32.85

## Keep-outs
Top Side:
  lines w0.4: 4.5,-8 4.5,-3.75 5,-3.25 5,-2.75 4.5,-2.25 4.5,26.25 5.25,27 5.25,29.75 4.5,30.5 4.5,32.75 ; 4.5,5 8,5 8.5,4.5 12,4.5 ; 4.5,19.75 8.75,19.75 10.5,18
  lines w0.8: 8.75,32.75 8.75,25.75 11.75,24 11.75,22.5 13.5,20.75 16,20.75 16,19.5 13.5,19.5 12,18 10.75,18 10.75,15 10.126,14.376 10.126,13.124 10.75,12.5 10.75,8.5 12,7.25 12,4.75 12.25,4.5 12.25,3.5 11.5,2.5 11.5,1 10.5,0 10.5,-2.25 9.5,-3.25 9.5,-7.75
Mid Layer 1:
  lines w0.4: 4.5,-8 4.5,-3.75 5,-3.25 5,-2.75 4.5,-2.25 4.5,26.25 5.25,27 5.25,29.75 4.5,30.5 4.5,32.75 ; 4.5,5 8,5 8.5,4.5 12,4.5 ; 4.5,19.75 8.75,19.75 10.5,18
  lines w0.8: 8.75,32.75 8.75,25.75 11.75,24 11.75,22.5 13.5,20.75 16,20.75 16,19.5 13.5,19.5 12,18 10.75,18 10.75,15 10.126,14.376 10.126,13.124 10.75,12.5 10.75,8.5 12,7.25 12,4.75 12.25,4.5 12.25,3.5 11.5,2.5 11.5,1 10.5,0 10.5,-2.25 9.5,-3.25 9.5,-7.75
Mid Layer 2:
  lines w0.4: 9.5,-8 9.5,-3.25 11.25,-1.5
Mid Layer 3:
  lines w0.4: 9.5,-8 9.5,-3.25 11.25,-1.5
Mid Layer 6:
  lines w0.4: 5.25,4.5 11.757,4.5 ; 9.5,-8 9.5,-3.25 11.25,-1.5
Mid Layer 4:
  lines w0.4: 9.5,-8 9.5,-3.25 11.25,-1.5
Mid Layer 5:
  lines w0.4: 9.5,-8 9.5,-3.25 11.25,-1.5
Bottom Side:
  lines w0.4: 5.25,4.5 10.75,4.5 ; 9.5,-8 9.5,-3.25 11.25,-1.5

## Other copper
Top Side:
  text "'.Layer_Name'" at 65.401,30.652 h1
Mid Layer 1:
  text "'.Layer_Name'" at 65.401,29.437 h1
Mid Layer 2:
  text "'.Layer_Name'" at 65.401,28.222 h1
Mid Layer 3:
  text "'.Layer_Name'" at 65.401,27.006 h1
Mid Layer 6:
  text "'.Layer_Name'" at 65.401,23.366 h1
Mid Layer 4:
  text "'.Layer_Name'" at 65.401,25.794 h1
Mid Layer 5:
  text "'.Layer_Name'" at 65.401,24.581 h1
Bottom Side:
  text "'.Layer_Name'" at 65.401,19.891 h1

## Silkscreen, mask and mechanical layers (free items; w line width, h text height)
Top Overlay:
  text "SW1" at 28.602,1.014 h1.8
  text "'.Layer_Name'" at 65.401,-2.348 h1
Bottom Overlay:
  text "'.Layer_Name'" at 65.401,-3.571 h1
Top Paste:
  text "'.Layer_Name'" at 65.401,-4.774 h1
Bottom Paste:
  text "'.Layer_Name'" at 65.401,-5.809 h1
Top Solder:
  text "maxon" at -0.815,18.983 h0.8
  text "ESCON2" at -1.215,17.6 h0.8
  text "'.PCB unassembled'-'.PCB Eng Rev'" at -7.998,3.212 h0.8
  text "'.Layer_Name'" at 65.401,-7.023 h1
Bottom Solder:
  text "'.Layer_Name'" at 65.401,-8.07 h1
Board:
  the board outline again, w0.1
  text "'.Layer_Name'" at 65.401,17.643 h1
Dimensions:
  text "'.Layer_Name'" at 65.401,16.608 h1
Sheet:
  drawing of 22 lines, arcs and shapes, not listed
  text "'.Layer_Name'" at 65.401,14.525 h1
  text "'.Application_BuildNumber'" at -16.968,-19.58 h1.5
  text "PCB P/N" at 23.285,-19.825 h2.5
  text "date:" at -8.914,-20.017 h2
  text "name:" at 6.036,-20.017 h2
  text "created" at -17.439,-22.716 h2
  text "03.05.2024" at -9.039,-22.942 h3
  text "MMAGBCH" at 5.898,-22.942 h3
  text "'.PCB unassembled'-'.PCB Eng Rev'" at 23.61,-24.592 h6
  text "modified" at -17.439,-25.764 h2
  text ".ModifiedDate" at -9.039,-25.981 h3
  text "MMAGFLLU" at 5.898,-25.981 h3
  text "Fabrication Data and Revision" at 23.285,-27.953 h2.5
  text "Date" at 80.187,-27.978 h2.5
  text "reviewed" at -17.439,-28.814 h2
  text "07.03.2025" at -9.039,-29.031 h3
  text "MMAGBCH" at 5.898,-29.031 h3
  text "'.Print_Date'" at 80.686,-30.678 h2.5
  text "CO-no." at -17.339,-32.245 h2.5
  text "'.CO_no'" at -9.539,-32.268 h3
  text "'.Print_Time'" at 80.686,-32.903 h2.5
  text "'.ItemAndRevision'" at 23.61,-33.142 h6
  text "Variant P/N" at 23.287,-37.553 h2.5
  text "'.VariantName'" at 23.372,-41.388 h5.4
  text "File:" at 23.161,-45.567 h2.5
  text ".Department" at -1.164,-45.642 h3
  text "'.Pcb_File_Name_No_Path'" at 27.837,-45.653 h2.5
Assembly Notes:
  text "'.Layer_Name'" at 65.4,18.678 h1
Fab Notes:
  text "'.Layer_Name'" at 65.401,15.572 h1
V Cut:
  text "'.Layer_Name'" at 65.402,13.479 h1
Top Assembly:
  text "'.Layer_Name'" at 65.401,9.835 h1
Bottom Assembly:
  text "'.Layer_Name'" at 65.401,8.623 h1
Top 3D Body:
  text "'.Layer_Name'" at 65.401,12.263 h1
Bottom 3D Body:
  text "'.Layer_Name'" at 65.401,11.048 h1
Top Courtyard:
  text "'.Layer_Name'" at 65.401,2.525 h1
Bottom Courtyard:
  text "'.Layer_Name'" at 65.401,1.301 h1
Top Component Outline:
  text "'.Layer_Name'" at 65.401,4.962 h1
Bottom Component Outline:
  text "'.Layer_Name'" at 65.401,3.748 h1
Top Terminal:
  text "'.Layer_Name'" at 65.401,-9.272 h1
Bottom Terminal:
  text "'.Layer_Name'" at 65.401,-10.308 h1
Top Test:
  text "'.Layer_Name'" at 65.401,-11.51 h1
Bottom Test:
  text "'.Layer_Name'" at 65.401,-12.546 h1
Top Thermal:
  text "'.Layer_Name'" at 65.401,-13.748 h1
Bottom Thermal:
  text "'.Layer_Name'" at 65.401,-14.784 h1
Top Coating:
  text "'.Layer_Name'" at 65.401,7.399 h1
Bottom Coating:
  text "'.Layer_Name'" at 65.401,6.176 h1
Top Designator:
  text "'.Layer_Name'" at 65.401,0.089 h1
Bottom Designator:
  text "'.Layer_Name'" at 65.401,-1.124 h1
Top Document Header:
  text "PCB P/N: '.PCB unassembled'-'.PCB Eng Rev'" at 42.51,-10.488 h1
  text "'.ItemAndRevision'" at 42.51,-11.494 h1
  text "Variant: '.VariantName'" at 42.51,-12.501 h1
  text "Variant Name: '.Variant_Description'" at 42.51,-13.513 h1
Bottom Document Header:
  text "PCB P/N: '.PCB unassembled'-'.PCB Eng Rev'" at 42,-10.487 h1
  text "'.ItemAndRevision'" at 42,-11.493 h1
  text "Variant: '.VariantName'" at 42,-12.5 h1
  text "Variant Name: '.Variant_Description'" at 42,-13.512 h1
Auxiliary Line:
  text "'.Layer_Name'" at 65.4,-15.996 h1

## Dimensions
2.75,30.5 to -10.75,32.85 on Dimensions
2.75,30.5 to 0,22.5 on Dimensions
0,22.5 to -10.75,-8.15 on Dimensions
54.75,32.85 to -10.75,32.85 on Dimensions
-10.75,-8.15 to -10.75,32.85 on Dimensions
-10.75,32.85 to -10.75,-8.15 on Dimensions
43.2,-0.35 to 0,0 on Dimensions
43.2,24.7 to 43.2,0 on Dimensions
